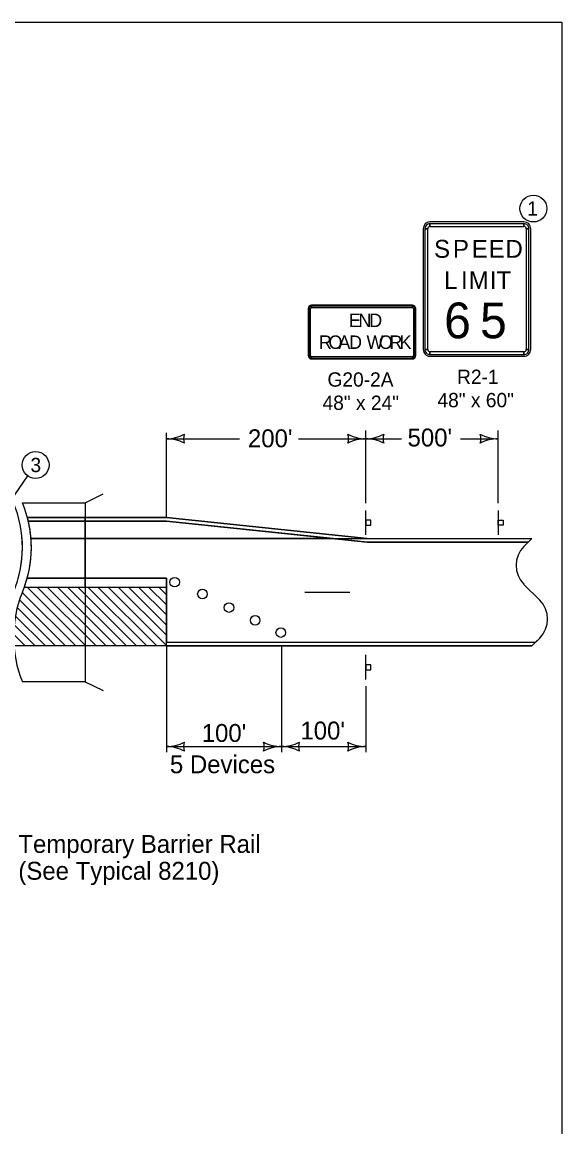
# Model space of a CAD drawing. Extents: x 10133 to 2270741, y 5363 to 1733450.
# Drawn here: x 30665 to 31268, y 8710 to 9944 of the extents above; entities that cross this region are included whole.
import ezdxf

# ---------------------------------------------------------------- set-up
doc = ezdxf.new("R2010")
doc.units = 0
for name, color, linetype in [('dsnNonPlotable', 7, 'Continuous'), ('dsnShtPlotShapeBatchPrint', 7, 'Continuous'), ('dsnStdBorder', 7, 'Continuous'), ('Level 12', 7, 'Continuous'), ('Level 2', 7, 'Continuous'), ('SheetBorder', 7, 'Continuous'), ('SheetText', 7, 'Continuous')]:
    doc.layers.add(name, color=color, linetype=linetype)

msp = doc.modelspace()

# ---------------------------------------------------------------- linework, layer by layer
at = {"layer": 'dsnNonPlotable'}
for p, q in [((30665.2, 9407.1), (30735.2, 9407.1)), ((30735.2, 9407.1), (30755.2, 9417.1)), ((30671.8, 9386.6), (30826, 9386.6)), ((30826, 9386.6), (31050.2, 9363.1)), ((30674.8, 9367.1), (31050.2, 9367.1)), ((31234, 9367.1), (31225.2, 9358.3)), ((30826, 9322.8), (30670.6, 9322.8)), ((30826, 9312.8), (30826, 9322.8)), ((30667.4, 9312.8), (30826, 9312.8)), ((31225.2, 9315.8), (31242.8, 9298.3)), ((31242.8, 9255.8), (31234, 9247.1)), ((30735.2, 9207.1), (30755.2, 9197.1))]:
    msp.add_line(p, q, dxfattribs=at)
for points in [[(30735.2, 9407.1), (30735.2, 9207.1), (30665.2, 9207.1)], [(31050.2, 9363.1), (31230, 9363.1)], [(30683.7, 9322.8), (30670.6, 9322.8)], [(30667.4, 9312.8), (30680.5, 9312.8)], [(30980.6, 9307.1), (31030.6, 9307.1)], [(30826, 9251.1), (31238, 9251.1)]]:
    msp.add_lwpolyline(points, dxfattribs=at)
for centre, radius, start, end in [((30535.2, 9357.1), 130, 337.3801, 22.6199), ((30545.2, 9357.1), 130, 337.3801, 22.6199), ((31246.4, 9337.1), 30, 135, 225), ((30785.2, 9257.1), 130, 157.3801, 202.6199), ((31221.6, 9277.1), 30, 315, 45)]:
    msp.add_arc(centre, radius, start, end, dxfattribs=at)
at = {"layer": 'dsnShtPlotShapeBatchPrint'}
msp.add_circle((31235.7, 9735.7), 15, dxfattribs=at)
at = {"layer": 'dsnStdBorder'}
for p, q in [((31225.2, 9720.7), (31120.2, 9720.7)), ((31120.2, 9715.7), (31120.2, 9718.8)), ((31225.2, 9718.8), (31225.2, 9715.7)), ((31112.7, 9713.2), (31112.7, 9578.2)), ((31114.6, 9713.2), (31117.7, 9713.2)), ((31227.7, 9713.2), (31230.8, 9713.2)), ((31232.7, 9578.2), (31232.7, 9713.2)), ((30984.3, 9623.9), (30984.3, 9571.4)), ((30985.3, 9623.9), (30986.8, 9623.9)), ((31100.6, 9627.7), (30988.1, 9627.7)), ((30988.1, 9625.2), (30988.1, 9626.7)), ((31100.6, 9626.7), (31100.6, 9625.2)), ((31101.8, 9623.9), (31103.4, 9623.9)), ((31104.3, 9571.4), (31104.3, 9623.9)), ((30986.8, 9571.4), (30985.3, 9571.4)), ((30988.1, 9568.6), (30988.1, 9570.2)), ((30988.1, 9567.7), (31100.6, 9567.7)), ((31100.6, 9570.2), (31100.6, 9568.6)), ((31103.4, 9571.4), (31101.8, 9571.4)), ((31117.7, 9578.2), (31114.6, 9578.2)), ((31120.2, 9572.5), (31120.2, 9575.7)), ((31120.2, 9570.7), (31225.2, 9570.7)), ((31225.2, 9575.7), (31225.2, 9572.5)), ((31230.8, 9578.2), (31227.7, 9578.2)), ((31048.6, 9371), (31048.6, 9398.5)), ((31196.2, 9398.5), (31196.2, 9371)), ((30826, 9386.6), (31050.2, 9363.1)), ((31050.2, 9363.1), (31230, 9363.1)), ((30683.7, 9322.8), (30670.6, 9322.8)), ((30735.2, 9322.8), (30683.7, 9322.8)), ((30826, 9322.8), (30735.2, 9322.8)), ((30735.2, 9322.8), (30735.2, 9312.8)), ((30735.2, 9312.8), (30735.2, 9322.8)), ((30826, 9312.8), (30826, 9322.8)), ((30667.4, 9312.8), (30680.5, 9312.8)), ((30670.4, 9312.8), (30736.1, 9247.1)), ((30680.5, 9312.8), (30735.2, 9312.8)), ((30681.7, 9312.8), (30747.4, 9247.1)), ((30693, 9312.8), (30758.7, 9247.1)), ((30704.3, 9312.8), (30770, 9247.1)), ((30715.6, 9312.8), (30781.4, 9247.1)), ((30726.9, 9312.8), (30792.7, 9247.1)), ((30735.2, 9312.8), (30826, 9312.8)), ((30738.3, 9312.8), (30804, 9247.1)), ((30749.6, 9312.8), (30815.3, 9247.1)), ((30760.9, 9312.8), (30826, 9247.7)), ((30772.2, 9312.8), (30826, 9259)), ((30783.5, 9312.8), (30826, 9270.3)), ((30794.8, 9312.8), (30826, 9281.6)), ((30806.1, 9312.8), (30826, 9293)), ((30817.4, 9312.8), (30826, 9304.3)), ((30826, 9247.1), (30826, 9312.8)), ((30662, 9298.5), (30713.5, 9247.1)), ((30665.1, 9306.8), (30724.8, 9247.1)), ((30659.4, 9289.8), (30702.2, 9247.1)), ((30655.9, 9270.7), (30679.5, 9247.1)), ((30657.3, 9280.6), (30690.8, 9247.1)), ((30655.2, 9260), (30668.2, 9247.1)), ((30736.1, 9247.1), (30735.2, 9248)), ((30735.2, 9248), (30735.2, 9247.1)), ((30735.2, 9247.1), (30736.1, 9247.1)), ((31048.6, 9209.5), (31048.6, 9237))]:
    msp.add_line(p, q, dxfattribs=at)
for points in [[(31225.2, 9718.8), (31120.2, 9718.8), (31120.2, 9715.7), (31225.2, 9715.7), (31225.2, 9718.8)], [(31114.6, 9713.2), (31114.6, 9578.2), (31117.7, 9578.2), (31117.7, 9713.2), (31114.6, 9713.2)], [(31230.8, 9578.2), (31230.8, 9713.2), (31227.7, 9713.2), (31227.7, 9578.2), (31230.8, 9578.2)], [(30985.3, 9623.9), (30985.3, 9571.4), (30986.8, 9571.4), (30986.8, 9623.9), (30985.3, 9623.9)], [(31100.6, 9626.7), (30988.1, 9626.7), (30988.1, 9625.2), (31100.6, 9625.2), (31100.6, 9626.7)], [(31103.4, 9571.4), (31103.4, 9623.9), (31101.8, 9623.9), (31101.8, 9571.4), (31103.4, 9571.4)], [(30988.1, 9568.6), (31100.6, 9568.6), (31100.6, 9570.2), (30988.1, 9570.2), (30988.1, 9568.6)], [(31120.2, 9572.5), (31225.2, 9572.5), (31225.2, 9575.7), (31120.2, 9575.7), (31120.2, 9572.5)], [(31048.7, 9387.4), (31048.7, 9381.8), (31054.3, 9381.8), (31054.3, 9387.4)], [(31196.3, 9382), (31196.3, 9387.6), (31201.9, 9387.6), (31201.9, 9382)], [(31048.7, 9226), (31048.7, 9220.3), (31054.3, 9220.3), (31054.3, 9226)]]:
    msp.add_lwpolyline(points, close=True, dxfattribs=at)
for centre in [(30835.2, 9318.3), (30835.2, 9318.3), (30866.2, 9305), (30866.2, 9305), (30895.8, 9289.9), (30895.8, 9289.9), (30925.1, 9275.6), (30925.1, 9275.6), (30953.7, 9262), (30953.7, 9262)]:
    msp.add_circle(centre, 5.37, dxfattribs=at)
for centre, radius, start, end in [((31120.2, 9713.2), 7.5, 90.0002, 179.9998), ((31120.2, 9713.2), 5.62, 90.0002, 179.9998), ((31120.2, 9713.2), 2.5, 90.0002, 179.9998), ((31225.2, 9713.2), 7.5, 0, 90.0002), ((31225.2, 9713.2), 5.62, 0, 90.0002), ((31225.2, 9713.2), 2.5, 0, 90.0002), ((30988.1, 9623.9), 3.75, 90.0002, 179.9998), ((30988.1, 9623.9), 2.81, 90.0002, 179.9998), ((30988.1, 9623.9), 1.25, 90.0002, 179.9998), ((31100.6, 9623.9), 3.75, 0, 90.0002), ((31100.6, 9623.9), 2.81, 0, 90.0002), ((31100.6, 9623.9), 1.25, 0, 90.0002), ((30988.1, 9571.4), 3.75, 179.9998, 270.0001), ((30988.1, 9571.4), 2.81, 179.9998, 270.0001), ((30988.1, 9571.4), 1.25, 179.9998, 270.0001), ((31100.6, 9571.4), 3.75, 270.0001, 0.0003), ((31100.6, 9571.4), 2.81, 270.0001, 0.0003), ((31100.6, 9571.4), 1.25, 270.0001, 0.0003), ((31120.2, 9578.2), 7.5, 179.9998, 270.0001), ((31120.2, 9578.2), 5.62, 179.9998, 270.0001), ((31120.2, 9578.2), 2.5, 179.9998, 270.0001), ((31225.2, 9578.2), 7.5, 270.0001, 0.0003), ((31225.2, 9578.2), 5.62, 270.0001, 0.0003), ((31225.2, 9578.2), 2.5, 270.0001, 0.0003), ((30545.2, 9357.1), 130, 340.0918, 344.7168)]:
    msp.add_arc(centre, radius, start, end, dxfattribs=at)
at = {"layer": 'Level 12'}
for p, q in [((30826, 9390.6), (30826, 9485.1)), ((31048.6, 9406.5), (31048.6, 9487.7)), ((31196.2, 9406.5), (31196.2, 9487.7)), ((30826, 9478.5), (30907.7, 9478.5)), ((30973.6, 9478.5), (31048.6, 9478.5)), ((31048.7, 9478.5), (31088.3, 9478.5)), ((31154.3, 9478.5), (31187.4, 9478.5)), ((30576.6, 9300.1), (30671.3, 9436.9)), ((30826, 9247.1), (30826, 9128.4)), ((30954.5, 9247.1), (30954.5, 9128.4)), ((31048.6, 9202.1), (31048.6, 9128.4)), ((30826, 9134.6), (31048.6, 9134.6))]:
    msp.add_line(p, q, dxfattribs=at)
msp.add_circle((30679.9, 9449.2), 15, dxfattribs=at)
for centre, radius, start, end in [((30826, 9521), 42.5, 270, 298.0725), ((30861.6, 9478.5), 16.4, 162.2666, 197.7334), ((31012.9, 9478.5), 16.4, 342.2666, 17.7334), ((31048.6, 9521), 42.5, 241.9275, 270), ((31048.6, 9521), 42.5, 270, 298.0725), ((31084.3, 9478.5), 16.4, 162.2666, 197.7334), ((31160.7, 9478.5), 16.4, 342.2666, 17.7334), ((31196.3, 9521), 42.5, 241.9275, 270), ((30826, 9436), 42.5, 61.9275, 90), ((31048.6, 9436), 42.5, 90, 118.0725), ((31048.6, 9436), 42.5, 61.9275, 90), ((31196.3, 9436), 42.5, 90, 118.0725), ((30826, 9177.1), 42.5, 270, 298.0725), ((30826, 9092.1), 42.5, 61.9275, 90), ((30861.6, 9134.6), 16.4, 162.2666, 197.7334), ((30918.8, 9134.6), 16.4, 342.2666, 17.7334), ((30954.4, 9177.1), 42.5, 241.9275, 270), ((30954.4, 9092.1), 42.5, 90, 118.0725), ((30954.4, 9177.1), 42.5, 270, 298.0725), ((30954.4, 9092.1), 42.5, 61.9275, 90), ((30990, 9134.6), 16.4, 162.2666, 197.7334), ((31012.9, 9134.6), 16.4, 342.2666, 17.7334), ((31048.6, 9177.1), 42.5, 241.9275, 270), ((31048.6, 9092.1), 42.5, 90, 118.0725)]:
    msp.add_arc(centre, radius, start, end, dxfattribs=at)
at = {"layer": 'Level 2'}
for p, q in [((30735.2, 9390.6), (30670.8, 9390.6)), ((30670.8, 9390.6), (30826, 9390.6)), ((30670.8, 9390.6), (30683.9, 9390.6)), ((30671.8, 9386.6), (30684.9, 9386.6)), ((30684.9, 9386.6), (30735.2, 9386.6)), ((30826, 9390.6), (30735.2, 9390.6)), ((30735.2, 9390.6), (30735.2, 9386.6)), ((30735.2, 9386.6), (30735.2, 9390.6)), ((30735.2, 9386.6), (30826, 9386.6)), ((30826, 9386.6), (30735.2, 9386.6)), ((30735.2, 9386.6), (30735.2, 9367.1)), ((30735.2, 9367.1), (30735.2, 9386.6)), ((30826, 9390.6), (31050.2, 9367.1)), ((31050.2, 9367.1), (30826, 9390.6)), ((30826, 9386.6), (31012, 9367.1)), ((31012, 9367.1), (30826, 9386.6)), ((30735.2, 9367.1), (30674.8, 9367.1)), ((30674.8, 9367.1), (30735.2, 9367.1)), ((30735.2, 9367.1), (30968.4, 9367.1)), ((30735.2, 9322.8), (30735.2, 9367.1)), ((30735.2, 9367.1), (30735.2, 9322.8)), ((30968.4, 9367.1), (31234, 9367.1)), ((30968.4, 9367.1), (31012, 9367.1)), ((31012, 9367.1), (31050.2, 9367.1)), ((31050.2, 9363.1), (31012, 9367.1)), ((31012, 9367.1), (31050.2, 9367.1)), ((31050.2, 9363.1), (31012, 9367.1)), ((31050.2, 9367.1), (31234, 9367.1)), ((31230, 9363.1), (31050.2, 9363.1)), ((31230, 9363.1), (31050.2, 9363.1)), ((31225.2, 9358.3), (31230, 9363.1)), ((31234, 9367.1), (31230, 9363.1)), ((30670.6, 9322.8), (30683.7, 9322.8)), ((30683.7, 9322.8), (30735.2, 9322.8)), ((30735.2, 9322.8), (30826, 9322.8)), ((30826, 9322.8), (30826, 9312.8)), ((30826, 9312.8), (30826, 9307.1)), ((30826, 9307.1), (30826, 9304.3)), ((31242.8, 9298.3), (31225.2, 9315.8)), ((30826, 9304.3), (30826, 9293)), ((30826, 9293), (30826, 9281.6)), ((30826, 9259), (30826, 9251.1)), ((30826, 9247.1), (30655.6, 9247.1)), ((30826, 9251.1), (31238, 9251.1)), ((30826, 9251.1), (31238, 9251.1)), ((31234, 9247.1), (30826, 9247.1)), ((30826, 9247.1), (31234, 9247.1)), ((31238, 9251.1), (31234, 9247.1)), ((31238, 9251.1), (31242.8, 9255.8))]:
    msp.add_line(p, q, dxfattribs=at)
for points in [[(30735.2, 9386.6), (30684.9, 9386.6), (30671.8, 9386.6)], [(31012, 9367.1), (30968.4, 9367.1), (30735.2, 9367.1)], [(30968.4, 9367.1), (30968.4, 9367.1)], [(31050.2, 9367.1), (31050.2, 9367.1)], [(31230, 9363.1), (31230, 9363.1)], [(31230, 9363.1), (31230, 9363.1)], [(30826, 9281.6), (30826, 9270.3), (30826, 9259)], [(30826, 9247.1), (30826, 9247.7), (30826, 9251.1)], [(31238, 9251.1), (31238, 9251.1)], [(31238, 9251.1), (31238, 9251.1)]]:
    msp.add_lwpolyline(points, dxfattribs=at)
for centre, radius, start, end in [((30545.2, 9357.1), 130, 13.1174, 14.9346), ((30545.2, 9357.1), 130, 4.4108, 13.1174), ((30535.2, 9357.1), 130, 344.7177, 4.4117), ((30545.2, 9357.1), 130, 344.7168, 4.4108), ((31246.4, 9337.1), 30, 135, 225), ((31221.6, 9277.1), 30, 315, 45)]:
    msp.add_arc(centre, radius, start, end, dxfattribs=at)
at = {"layer": 'SheetBorder'}
msp.add_lwpolyline([(28132.5, 9944), (31267.5, 9944), (31267.5, 7924), (28132.5, 7924)], close=True, dxfattribs=at)

# ---------------------------------------------------------------- texts
at = {"layer": 'dsnShtPlotShapeBatchPrint'}
msp.add_text('1', height=16, dxfattribs=at).set_placement((31228.7, 9727.7))
at = {"layer": 'dsnStdBorder'}
for s, height, p in [('S', 20, (31124.8, 9680.7)), ('P', 20, (31145.9, 9680.7)), ('E', 20, (31167, 9680.7)), ('E', 20, (31185.8, 9680.7)), ('D', 20, (31204.6, 9680.7)), ('L', 20, (31136.1, 9645.7)), ('I', 20, (31154.9, 9645.7)), ('M', 20, (31163.5, 9645.7)), ('I', 20, (31187.1, 9645.7)), ('T', 20, (31194.6, 9645.7)), ('6', 40, (31136.1, 9590.7)), ('5', 40, (31176.2, 9590.7)), ('E', 15, (31029.7, 9603.3)), ('N', 15, (31040.3, 9603.3)), ('D', 15, (31052.4, 9603.3)), ('R', 15, (30996.2, 9578.9)), ('O', 15, (31006.9, 9578.9)), ('A', 15, (31018, 9578.9)), ('D', 15, (31029.9, 9578.9)), ('W', 15, (31049.4, 9578.9)), ('O', 15, (31063.1, 9578.9)), ('R', 15, (31074.9, 9578.9)), ('K', 15, (31086.2, 9578.9)), ('R2-1', 16, (31150.5, 9539.7)), ('G20-2A', 16, (31005.8, 9536.7)), ('48" x 60"', 16, (31128.6, 9513.7)), ('48" x 24"', 16, (31000.3, 9510.7))]:
    msp.add_text(s, height=height, dxfattribs=at).set_placement(p)
at = {"layer": 'Level 12'}
for s, height, p in [("200'", 20, (30917, 9469)), ("500'", 20, (31095.2, 9469.9)), ('3', 16, (30674.2, 9441.2)), ("100'", 20, (30865.4, 9139.8)), ("100'", 20, (30975.6, 9142.5)), ('5 Devices', 20, (30829.9, 9104.8)), ('Temporary Barrier Rail', 20, (30660.7, 9015.8)), ('(See Typical 8210)', 20, (30660.7, 8985.8))]:
    msp.add_text(s, height=height, dxfattribs=at).set_placement(p)
at = {"layer": 'SheetText'}
for s, p in [('R2-1', (31150.5, 9539.7)), ('48" x 60"', (31128.6, 9513.7))]:
    msp.add_text(s, height=16, dxfattribs=at).set_placement(p)

doc.saveas('drawing.dxf')
